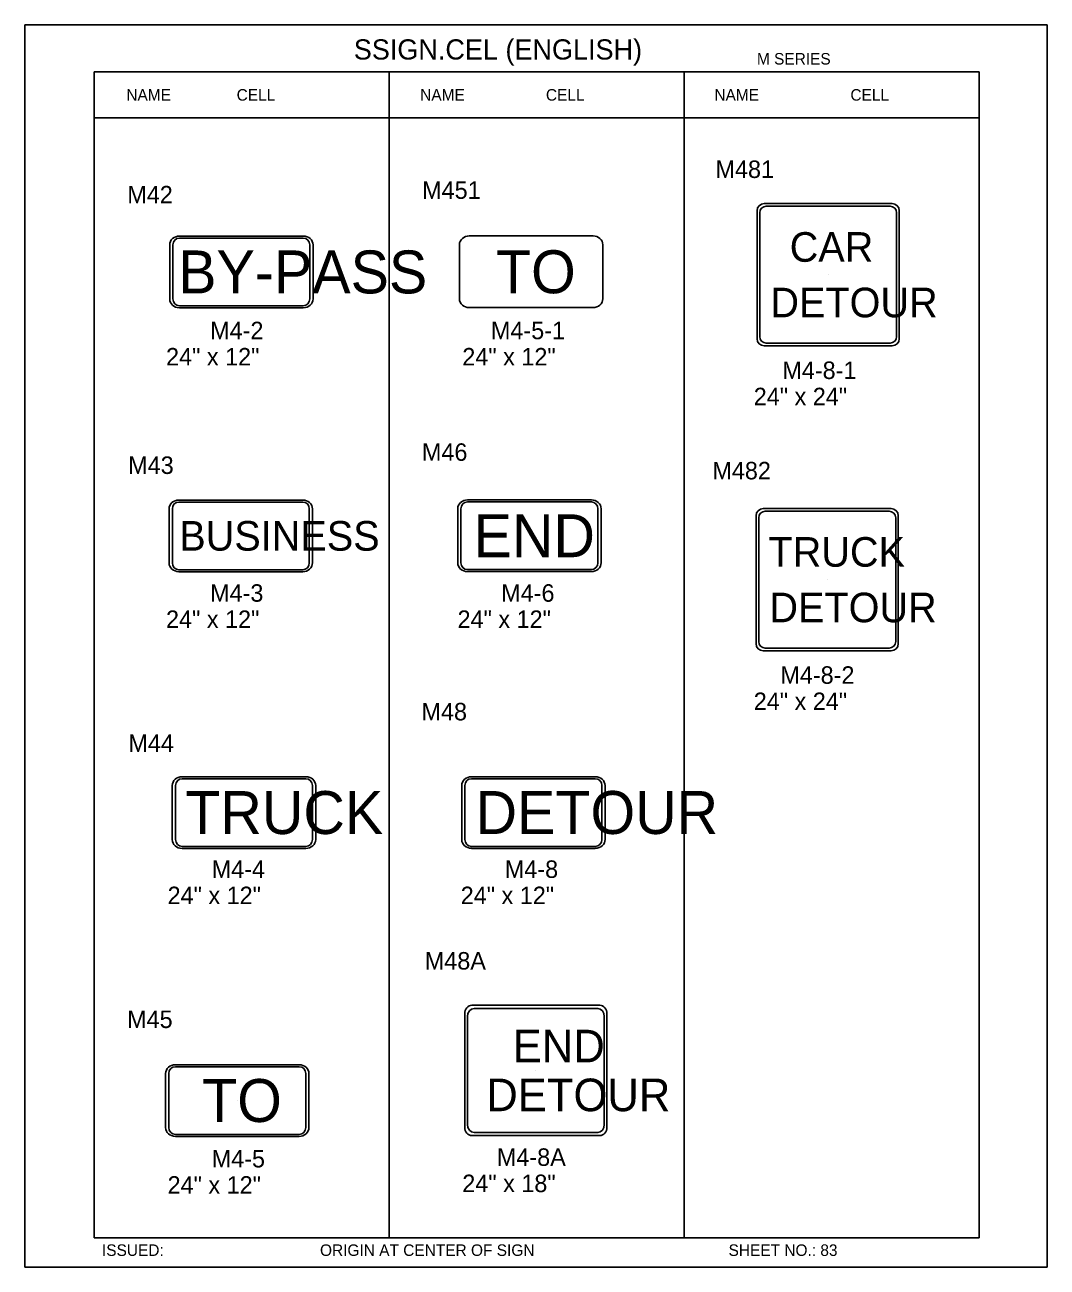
# Model space of a CAD drawing. Extents: x -5299 to 22597, y -19549 to -1808.
# Drawn here: x 8820 to 9521, y -5466 to -4614 of the extents above; entities that cross this region are included whole.
import ezdxf

# ---------------------------------------------------------------- set-up
doc = ezdxf.new("R2010")
doc.units = 0
for name, color, linetype in [('Level 1', 7, 'Continuous'), ('Level 2', 7, 'Continuous'), ('Level 3', 7, 'Continuous'), ('Level 61', 7, 'Continuous')]:
    doc.layers.add(name, color=color, linetype=linetype)

msp = doc.modelspace()

# ---------------------------------------------------------------- linework, layer by layer
at = {"layer": 'Level 1'}
for p, q in [((9474.04, -4645.77), (8867.02, -4645.77)), ((8867.02, -4645.77), (8867.02, -5445.77)), ((9069.36, -4645.77), (9069.36, -5445.77)), ((9271.7, -4645.77), (9271.7, -5445.77)), ((9474.04, -4645.77), (9474.04, -5445.77)), ((9474.04, -4677.44), (8867.02, -4677.44)), ((9326.52, -4736.26), (9414.3, -4736.26)), ((9327.96, -4738.07), (9412.85, -4738.07)), ((9321.64, -4828.92), (9321.64, -4741.14)), ((9323.45, -4827.47), (9323.45, -4742.58)), ((9417.36, -4742.58), (9417.36, -4827.47)), ((9419.17, -4741.14), (9419.17, -4828.92)), ((8967.98, -4783.1), (8967.98, -4783.1)), ((9166.71, -4783.01), (9166.71, -4783.01)), ((9370.41, -4785.03), (9370.41, -4785.03)), ((9412.85, -4831.98), (9327.96, -4831.98)), ((9414.3, -4833.79), (9326.52, -4833.79)), ((9320.97, -5038.16), (9320.97, -4950.38)), ((9322.78, -5036.72), (9322.78, -4951.83)), ((9325.85, -4945.51), (9413.63, -4945.51)), ((9327.29, -4947.32), (9412.18, -4947.32)), ((9416.69, -4951.83), (9416.69, -5036.72)), ((9418.5, -4950.38), (9418.5, -5038.16)), ((8967.61, -4964.19), (8967.61, -4964.19)), ((9165.55, -4964.12), (9165.55, -4964.12)), ((9369.74, -4994.27), (9369.74, -4994.27)), ((9369.74, -4994.27), (9369.74, -4994.27)), ((9413.63, -5043.04), (9325.85, -5043.04)), ((9412.18, -5041.23), (9327.29, -5041.23)), ((8969.78, -5154.05), (8969.78, -5154.05)), ((9168.25, -5154.01), (9168.25, -5154.01)), ((9121.17, -5369.78), (9121.17, -5292.25)), ((9126.05, -5286.29), (9213.82, -5286.29)), ((9127.53, -5288.53), (9212.38, -5288.53)), ((9218.7, -5292.25), (9218.7, -5369.78)), ((9123.01, -5367.99), (9123.01, -5294.04)), ((9216.89, -5294.04), (9216.89, -5367.99)), ((8965.18, -5351.63), (8965.18, -5351.63)), ((9213.82, -5375.74), (9126.05, -5375.74)), ((9212.38, -5373.5), (9127.53, -5373.5)), ((8867.02, -5445.77), (9474.04, -5445.77))]:
    msp.add_line(p, q, dxfattribs=at)
for centre, radius, start, end in [((9326.52, -4741.14), 4.88, 90, 180), ((9327.96, -4742.58), 4.51, 90, 180), ((9412.85, -4742.58), 4.51, 0, 90), ((9414.3, -4741.14), 4.88, 0, 90), ((9326.52, -4828.92), 4.88, 180, 270), ((9327.96, -4827.47), 4.51, 180, 270), ((9412.85, -4827.47), 4.51, 270, 0), ((9414.3, -4828.92), 4.88, 270, 0), ((9325.85, -4950.38), 4.88, 90, 180), ((9327.29, -4951.83), 4.51, 90, 180), ((9412.18, -4951.83), 4.51, 0, 90), ((9413.63, -4950.38), 4.88, 0, 90), ((9327.29, -5036.71), 4.51, 180, 270), ((9412.18, -5036.71), 4.51, 270, 0), ((9325.85, -5038.16), 4.88, 180, 270), ((9413.63, -5038.16), 4.88, 270, 0)]:
    msp.add_arc(centre, radius, start, end, dxfattribs=at)
for centre, major_axis, start_param, end_param in [((9126.04, -5292.25), (0, -5.96), 3.141593, 4.712389), ((9127.53, -5294.04), (0, -5.52), 3.141593, 4.712389), ((9212.38, -5294.04), (0, 5.52), 4.712389, 6.283185), ((9213.82, -5292.25), (0, 5.96), 4.712389, 6.283185), ((9126.04, -5369.78), (0, -5.96), 4.712389, 6.283185), ((9127.53, -5367.99), (0, -5.52), 4.712389, 6.283185), ((9212.38, -5367.99), (0, 5.52), 3.141593, 4.712389), ((9213.82, -5369.78), (0, -5.96), 0, 1.570796)]:
    msp.add_ellipse(centre, major_axis=major_axis, ratio=0.817773, start_param=start_param, end_param=end_param, dxfattribs=at)
at = {"layer": 'Level 3'}
for p, q in [((8918.82, -4801.68), (8918.82, -4764.53)), ((8921.03, -4801.68), (8921.03, -4764.53)), ((8925.54, -4758.52), (9010.43, -4758.52)), ((8925.54, -4759.89), (9010.43, -4759.89)), ((9014.94, -4764.53), (9014.94, -4801.68)), ((9017.15, -4764.53), (9017.15, -4801.68)), ((9117.54, -4801.59), (9117.54, -4764.43)), ((9124.27, -4758.43), (9209.16, -4758.43)), ((9215.88, -4764.43), (9215.88, -4801.59)), ((9010.43, -4806.32), (8925.54, -4806.32)), ((9010.43, -4807.69), (8925.54, -4807.69)), ((9209.16, -4807.6), (9124.27, -4807.6)), ((8925.16, -4939.61), (9010.05, -4939.61)), ((8925.16, -4940.98), (9010.05, -4940.98)), ((9123.1, -4939.54), (9207.99, -4939.54)), ((9123.1, -4940.9), (9207.99, -4940.9)), ((8918.44, -4982.77), (8918.44, -4945.62)), ((8920.65, -4982.77), (8920.65, -4945.62)), ((9014.56, -4945.62), (9014.56, -4982.77)), ((9016.77, -4945.62), (9016.77, -4982.77)), ((9116.38, -4982.7), (9116.38, -4945.55)), ((9118.59, -4982.7), (9118.59, -4945.55)), ((9212.5, -4945.55), (9212.5, -4982.7)), ((9214.72, -4945.55), (9214.72, -4982.7)), ((9010.05, -4987.41), (8925.16, -4987.41)), ((9010.05, -4988.78), (8925.16, -4988.78)), ((9207.99, -4987.34), (9123.1, -4987.34)), ((9207.99, -4988.71), (9123.1, -4988.71)), ((8927.33, -5129.46), (9012.22, -5129.46)), ((8927.33, -5130.83), (9012.22, -5130.83)), ((9125.81, -5129.43), (9210.69, -5129.43)), ((9125.81, -5130.8), (9210.69, -5130.8)), ((8920.61, -5172.62), (8920.61, -5135.47)), ((8922.82, -5172.62), (8922.82, -5135.47)), ((9016.73, -5135.47), (9016.73, -5172.62)), ((9018.94, -5135.47), (9018.94, -5172.62)), ((9119.08, -5172.59), (9119.08, -5135.44)), ((9121.3, -5172.59), (9121.3, -5135.44)), ((9215.2, -5135.44), (9215.2, -5172.59)), ((9217.42, -5135.44), (9217.42, -5172.59)), ((9012.22, -5177.26), (8927.33, -5177.26)), ((9012.22, -5178.63), (8927.33, -5178.63)), ((9210.69, -5177.23), (9125.81, -5177.23)), ((9210.69, -5178.6), (9125.81, -5178.6)), ((8922.74, -5327.04), (9007.63, -5327.04)), ((8916.02, -5370.21), (8916.02, -5333.05)), ((8918.23, -5370.21), (8918.23, -5333.05)), ((8922.74, -5328.41), (9007.63, -5328.41)), ((9012.14, -5333.05), (9012.14, -5370.21)), ((9014.35, -5333.05), (9014.35, -5370.21)), ((9169.95, -5331.01), (9169.95, -5331.01)), ((9007.63, -5374.85), (8922.74, -5374.85)), ((9007.63, -5376.21), (8922.74, -5376.21))]:
    msp.add_line(p, q, dxfattribs=at)
for centre, major_axis, ratio, start_param, end_param in [((8925.54, -4764.53), (6.72, 0), 0.893242, 1.570796, 3.141593), ((8925.54, -4764.53), (0, -4.64), 0.972176, 3.141593, 4.712389), ((9010.43, -4764.53), (-6.72, 0), 0.893242, 3.141593, 4.712389), ((9010.43, -4764.53), (0, 4.64), 0.972176, 4.712389, 6.283185), ((9124.27, -4764.43), (6.72, 0), 0.893242, 1.570796, 3.141593), ((9209.16, -4764.43), (-6.72, 0), 0.893242, 3.141593, 4.712389), ((8925.54, -4801.68), (6.72, 0), 0.893242, 3.141593, 4.712389), ((8925.54, -4801.68), (0, -4.64), 0.972176, 4.712389, 6.283185), ((9010.43, -4801.68), (0, 4.64), 0.972176, 3.141593, 4.712389), ((9010.43, -4801.68), (-6.72, 0), 0.893242, 1.570796, 3.141593), ((9124.27, -4801.59), (6.72, 0), 0.893242, 3.141593, 4.712389), ((9209.16, -4801.59), (-6.72, 0), 0.893242, 1.570796, 3.141593), ((8925.16, -4945.62), (6.72, 0), 0.893242, 1.570796, 3.141593), ((8925.16, -4945.62), (0, -4.64), 0.972176, 3.141593, 4.712389), ((9010.05, -4945.62), (-6.72, 0), 0.893242, 3.141593, 4.712389), ((9010.05, -4945.62), (0, 4.64), 0.972176, 4.712389, 6.283185), ((9123.1, -4945.55), (6.72, 0), 0.893242, 1.570796, 3.141593), ((9123.1, -4945.55), (0, -4.64), 0.972176, 3.141593, 4.712389), ((9207.99, -4945.55), (-6.72, 0), 0.893242, 3.141593, 4.712389), ((9207.99, -4945.55), (0, 4.64), 0.972176, 4.712389, 6.283185), ((8925.16, -4982.77), (6.72, 0), 0.893242, 3.141593, 4.712389), ((8925.16, -4982.77), (0, -4.64), 0.972176, 4.712389, 6.283185), ((9010.05, -4982.77), (0, 4.64), 0.972176, 3.141593, 4.712389), ((9010.05, -4982.77), (-6.72, 0), 0.893242, 1.570796, 3.141593), ((9123.1, -4982.7), (6.72, 0), 0.893242, 3.141593, 4.712389), ((9123.1, -4982.7), (0, -4.64), 0.972176, 4.712389, 6.283185), ((9207.99, -4982.7), (0, 4.64), 0.972176, 3.141593, 4.712389), ((9207.99, -4982.7), (-6.72, 0), 0.893242, 1.570796, 3.141593), ((8927.33, -5135.47), (6.72, 0), 0.893242, 1.570796, 3.141593), ((8927.33, -5135.47), (0, -4.64), 0.972176, 3.141593, 4.712389), ((9012.22, -5135.47), (-6.72, 0), 0.893242, 3.141593, 4.712389), ((9012.22, -5135.47), (0, 4.64), 0.972176, 4.712389, 6.283185), ((9125.81, -5135.44), (6.72, 0), 0.893242, 1.570796, 3.141593), ((9125.81, -5135.44), (0, -4.64), 0.972176, 3.141593, 4.712389), ((9210.69, -5135.44), (-6.72, 0), 0.893242, 3.141593, 4.712389), ((9210.69, -5135.44), (0, 4.64), 0.972176, 4.712389, 6.283185), ((8927.33, -5172.62), (6.72, 0), 0.893242, 3.141593, 4.712389), ((8927.33, -5172.62), (0, -4.64), 0.972176, 4.712389, 6.283185), ((9012.22, -5172.62), (0, 4.64), 0.972176, 3.141593, 4.712389), ((9012.22, -5172.62), (-6.72, 0), 0.893242, 1.570796, 3.141593), ((9125.81, -5172.59), (6.72, 0), 0.893242, 3.141593, 4.712389), ((9125.81, -5172.59), (0, -4.64), 0.972176, 4.712389, 6.283185), ((9210.69, -5172.59), (0, 4.64), 0.972176, 3.141593, 4.712389), ((9210.69, -5172.59), (-6.72, 0), 0.893242, 1.570796, 3.141593), ((8922.74, -5333.05), (6.72, 0), 0.893242, 1.570796, 3.141593), ((9007.63, -5333.05), (-6.72, 0), 0.893242, 3.141593, 4.712389), ((8922.74, -5333.05), (0, -4.64), 0.972176, 3.141593, 4.712389), ((9007.63, -5333.05), (0, 4.64), 0.972176, 4.712389, 6.283185), ((8922.74, -5370.21), (6.72, 0), 0.893242, 3.141593, 4.712389), ((8922.74, -5370.21), (0, -4.64), 0.972176, 4.712389, 6.283185), ((9007.63, -5370.21), (0, 4.64), 0.972176, 3.141593, 4.712389), ((9007.63, -5370.21), (-6.72, 0), 0.893242, 1.570796, 3.141593)]:
    msp.add_ellipse(centre, major_axis=major_axis, ratio=ratio, start_param=start_param, end_param=end_param, dxfattribs=at)
at = {"layer": 'Level 61'}
msp.add_lwpolyline([(8819.51, -5465.96), (9520.56, -5465.96), (9520.56, -4613.58), (8819.51, -4613.58)], close=True, dxfattribs=at)

# ---------------------------------------------------------------- texts
at = {"layer": 'Level 1'}
for s, height, p in [('CAR', 20.319, (9344.01, -4776.14)), ('BY-PASS', 29.463, (8924.67, -4797.84)), ('TO', 29.463, (9142.58, -4797.74)), ('DETOUR', 20.319, (9330.76, -4814.24)), ('END', 29.463, (9127.27, -4978.86)), ('BUSINESS', 20.319, (8925.41, -4974.35)), ('TRUCK', 20.319, (9329.49, -4985.38)), ('DETOUR', 20.319, (9330.09, -5023.48)), ('TRUCK', 29.463, (8929.53, -5168.78)), ('DETOUR', 29.463, (9128.6, -5168.74)), ('END', 22.351, (9154.11, -5325.43)), ('TO', 29.463, (8941.06, -5366.36)), ('DETOUR', 22.351, (9135.97, -5358.95))]:
    msp.add_text(s, height=height, dxfattribs=at).set_placement(p)
at = {"layer": 'Level 2'}
for s, p in [('M481', (9293.12, -4718.65)), ('M451', (9091.95, -4732.97)), ('M42', (8889.75, -4736.07)), ('M46', (9091.79, -4912.72)), ('M43', (8890.38, -4921.72)), ('M482', (9290.98, -4925.43)), ('M48', (9091.5, -5090.79)), ('M44', (8890.5, -5112.49)), ('M48A', (9093.77, -5261.77)), ('M45', (8889.63, -5301.89))]:
    msp.add_text(s, height=12, dxfattribs=at).set_placement(p)
at = {"layer": 'Level 3'}
for s, height, p in [('SSIGN.CEL (ENGLISH)', 13.8566, (9045.09, -4637.38)), ('M SERIES', 7.918, (9321.54, -4640.82)), ('NAME', 7.918, (8889.09, -4665.6)), ('CELL', 7.918, (8964.75, -4665.6)), ('NAME', 7.918, (9090.63, -4665.6)), ('CELL', 7.918, (9176.83, -4665.6)), ('NAME', 7.918, (9292.39, -4665.6)), ('CELL', 7.918, (9385.65, -4665.6)), ('M4-2', 12, (8946.57, -4829.28)), ('M4-5-1', 12, (9139.11, -4829.28)), ('24" x 12"', 12, (8916.34, -4847.28)), ('24" x 12"', 12, (9119.51, -4847.28)), ('M4-8-1', 12, (9338.96, -4856.57)), ('24" x 24"', 12, (9319.36, -4874.57)), ('M4-3', 12, (8946.54, -5009.39)), ('M4-6', 12, (9146.15, -5009.39)), ('24" x 12"', 12, (8916.31, -5027.39)), ('24" x 12"', 12, (9116.25, -5027.39)), ('M4-8-2', 12, (9337.59, -5065.69)), ('24" x 24"', 12, (9319.36, -5083.69)), ('M4-4', 12, (8947.63, -5198.88)), ('M4-8', 12, (9148.65, -5198.88)), ('24" x 12"', 12, (8917.4, -5216.88)), ('24" x 12"', 12, (9118.41, -5216.88)), ('M4-5', 12, (8947.63, -5397.55)), ('M4-8A', 12, (9143.21, -5396.47)), ('24" x 12"', 12, (8917.4, -5415.55)), ('24" x 18"', 12, (9119.49, -5414.47)), ('ISSUED:', 7.918, (8872.39, -5458.26)), ('ORIGIN AT CENTER OF SIGN', 7.9181, (9021.92, -5458.26)), ('SHEET NO.: 83', 7.918, (9302.08, -5458.26))]:
    msp.add_text(s, height=height, dxfattribs=at).set_placement(p)

doc.saveas('drawing.dxf')
